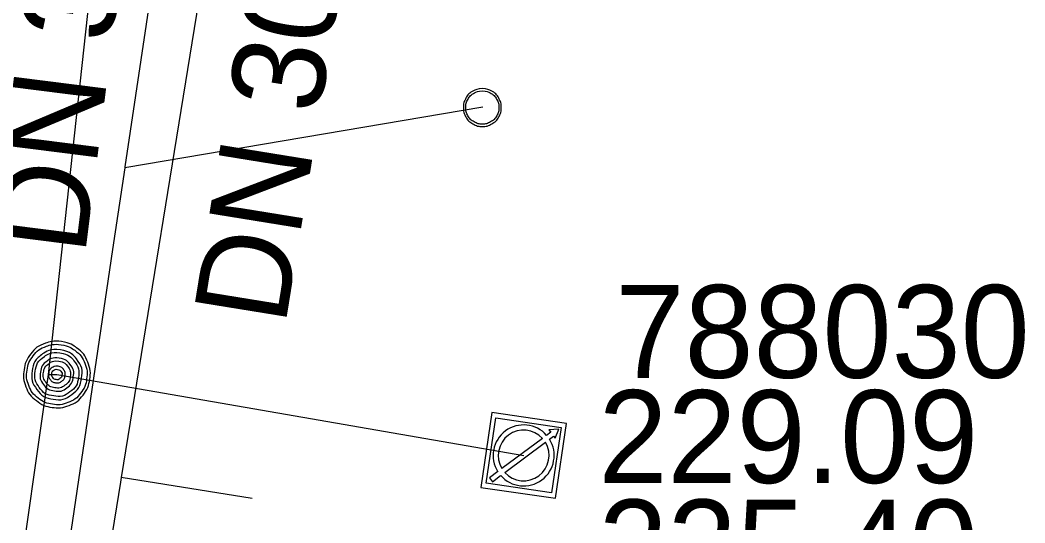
# Model space of a CAD drawing. Extents: x -595129 to -593591, y -1168385 to -1166898.
# Drawn here: x -594630.48 to -594615.33, y -1167150.4 to -1167142.81 of the extents above; entities that cross this region are included whole.
import ezdxf

# ---------------------------------------------------------------- set-up
doc = ezdxf.new("R2010")
doc.units = 0
for name, color, linetype in [('DA Kanalizační stoka popis', 7, 'Continuous'), ('Default', 7, 'Continuous'), ('Identifikace', 7, 'Continuous'), ('Kanalizační přípojka', 7, 'Continuous'), ('Kanalizační stoka', 7, 'Continuous'), ('Popis šachty', 7, 'Continuous'), ('V Odběrné místo', 7, 'Continuous'), ('V Přípojka', 7, 'Continuous'), ('V Řad', 7, 'Continuous')]:
    doc.layers.add(name, color=color, linetype=linetype)

msp = doc.modelspace()

# ---------------------------------------------------------------- linework, layer by layer
at = {"layer": 'Default'}
for points in [[(-594623.515, -1167143.849), (-594623.444, -1167143.849), (-594623.375, -1167143.885), (-594623.307, -1167143.922), (-594623.269, -1167143.991), (-594623.23, -1167144.059), (-594623.23, -1167144.134), (-594623.23, -1167144.208), (-594623.268, -1167144.276), (-594623.305, -1167144.343), (-594623.373, -1167144.381), (-594623.441, -1167144.419), (-594623.515, -1167144.419), (-594623.589, -1167144.419), (-594623.657, -1167144.381), (-594623.725, -1167144.343), (-594623.763, -1167144.276), (-594623.8, -1167144.208), (-594623.8, -1167144.134), (-594623.8, -1167144.059), (-594623.762, -1167143.991), (-594623.724, -1167143.922), (-594623.656, -1167143.885), (-594623.587, -1167143.849), (-594623.515, -1167143.849)], [(-594623.515, -1167143.884), (-594623.578, -1167143.884), (-594623.638, -1167143.916), (-594623.698, -1167143.948), (-594623.731, -1167144.008), (-594623.765, -1167144.068), (-594623.765, -1167144.134), (-594623.765, -1167144.199), (-594623.732, -1167144.258), (-594623.699, -1167144.317), (-594623.639, -1167144.35), (-594623.58, -1167144.383), (-594623.515, -1167144.383), (-594623.45, -1167144.383), (-594623.391, -1167144.35), (-594623.331, -1167144.317), (-594623.299, -1167144.258), (-594623.266, -1167144.199), (-594623.266, -1167144.134), (-594623.266, -1167144.068), (-594623.3, -1167144.008), (-594623.333, -1167143.948), (-594623.393, -1167143.916), (-594623.453, -1167143.884), (-594623.515, -1167143.884)], [(-594629.858, -1167147.664), (-594629.733, -1167147.682), (-594629.624, -1167147.764), (-594629.515, -1167147.845), (-594629.465, -1167147.974), (-594629.416, -1167148.103), (-594629.435, -1167148.232), (-594629.454, -1167148.361), (-594629.536, -1167148.469), (-594629.619, -1167148.577), (-594629.746, -1167148.626), (-594629.874, -1167148.674), (-594630.003, -1167148.655), (-594630.131, -1167148.636), (-594630.239, -1167148.553), (-594630.348, -1167148.471), (-594630.396, -1167148.344), (-594630.444, -1167148.216), (-594630.425, -1167148.088), (-594630.406, -1167147.958), (-594630.322, -1167147.848), (-594630.238, -1167147.739), (-594630.111, -1167147.692), (-594629.983, -1167147.646), (-594629.858, -1167147.664)], [(-594629.865, -1167147.711), (-594629.978, -1167147.694), (-594630.094, -1167147.736), (-594630.21, -1167147.778), (-594630.286, -1167147.878), (-594630.362, -1167147.977), (-594630.379, -1167148.094), (-594630.396, -1167148.211), (-594630.352, -1167148.326), (-594630.309, -1167148.441), (-594630.211, -1167148.516), (-594630.112, -1167148.591), (-594629.996, -1167148.608), (-594629.879, -1167148.625), (-594629.763, -1167148.582), (-594629.647, -1167148.538), (-594629.573, -1167148.44), (-594629.498, -1167148.342), (-594629.481, -1167148.226), (-594629.464, -1167148.108), (-594629.509, -1167147.991), (-594629.554, -1167147.874), (-594629.653, -1167147.801), (-594629.752, -1167147.727), (-594629.865, -1167147.711)], [(-594629.877, -1167147.788), (-594629.72, -1167147.811), (-594629.628, -1167147.935), (-594629.536, -1167148.06), (-594629.559, -1167148.214), (-594629.581, -1167148.368), (-594629.706, -1167148.461), (-594629.83, -1167148.553), (-594629.985, -1167148.531), (-594630.138, -1167148.508), (-594630.231, -1167148.384), (-594630.324, -1167148.259), (-594630.301, -1167148.106), (-594630.279, -1167147.951), (-594630.155, -1167147.858), (-594630.031, -1167147.765), (-594629.877, -1167147.788)], [(-594629.883, -1167147.833), (-594630.019, -1167147.814), (-594630.127, -1167147.895), (-594630.236, -1167147.976), (-594630.256, -1167148.111), (-594630.275, -1167148.246), (-594630.195, -1167148.355), (-594630.114, -1167148.464), (-594629.978, -1167148.483), (-594629.843, -1167148.503), (-594629.734, -1167148.422), (-594629.625, -1167148.341), (-594629.606, -1167148.206), (-594629.586, -1167148.071), (-594629.667, -1167147.962), (-594629.747, -1167147.853), (-594629.883, -1167147.833)], [(-594629.894, -1167147.912), (-594629.79, -1167147.927), (-594629.729, -1167148.01), (-594629.667, -1167148.093), (-594629.682, -1167148.196), (-594629.697, -1167148.299), (-594629.78, -1167148.36), (-594629.864, -1167148.422), (-594629.967, -1167148.407), (-594630.069, -1167148.392), (-594630.131, -1167148.309), (-594630.193, -1167148.226), (-594630.178, -1167148.124), (-594630.163, -1167148.021), (-594630.08, -1167147.959), (-594629.998, -1167147.897), (-594629.894, -1167147.912)], [(-594629.901, -1167147.958), (-594629.985, -1167147.946), (-594630.052, -1167147.996), (-594630.119, -1167148.046), (-594630.132, -1167148.13), (-594630.144, -1167148.213), (-594630.094, -1167148.281), (-594630.043, -1167148.348), (-594629.96, -1167148.36), (-594629.877, -1167148.372), (-594629.809, -1167148.322), (-594629.741, -1167148.272), (-594629.729, -1167148.188), (-594629.717, -1167148.105), (-594629.767, -1167148.037), (-594629.817, -1167147.97), (-594629.901, -1167147.958)], [(-594629.912, -1167148.036), (-594629.86, -1167148.043), (-594629.829, -1167148.085), (-594629.799, -1167148.126), (-594629.806, -1167148.178), (-594629.814, -1167148.229), (-594629.855, -1167148.26), (-594629.897, -1167148.291), (-594629.949, -1167148.283), (-594629.999, -1167148.276), (-594630.03, -1167148.234), (-594630.061, -1167148.193), (-594630.054, -1167148.141), (-594630.046, -1167148.09), (-594630.005, -1167148.059), (-594629.964, -1167148.028), (-594629.912, -1167148.036)], [(-594629.919, -1167148.082), (-594629.951, -1167148.077), (-594629.977, -1167148.096), (-594630.003, -1167148.115), (-594630.008, -1167148.148), (-594630.012, -1167148.18), (-594629.993, -1167148.206), (-594629.974, -1167148.232), (-594629.942, -1167148.237), (-594629.909, -1167148.242), (-594629.883, -1167148.222), (-594629.858, -1167148.203), (-594629.853, -1167148.171), (-594629.848, -1167148.138), (-594629.867, -1167148.112), (-594629.886, -1167148.087), (-594629.919, -1167148.082)]]:
    msp.add_open_spline(points, degree=3, dxfattribs=at)
at = {"layer": 'Kanalizační přípojka'}
for points in [[(-594623.506, -1167144.13), (-594628.906, -1167145.043)], [(-594626.988, -1167150.032), (-594628.962, -1167149.712)]]:
    msp.add_lwpolyline(points, dxfattribs=at)
at = {"layer": 'Kanalizační stoka'}
for points in [[(-594622.469, -1167109.695), (-594623.816, -1167117.996), (-594623.863, -1167118.283), (-594624.053, -1167119.457), (-594624.101, -1167119.753), (-594624.29, -1167120.918), (-594624.328, -1167121.155), (-594625.261, -1167126.9), (-594625.299, -1167127.137), (-594625.978, -1167131.322), (-594626.013, -1167131.539), (-594626.244, -1167132.961), (-594626.246, -1167132.971), (-594626.81, -1167136.445), (-594626.874, -1167136.84), (-594627.277, -1167139.327), (-594627.291, -1167139.416), (-594627.748, -1167142.23), (-594627.762, -1167142.318), (-594628.962, -1167149.712), (-594628.973, -1167149.781), (-594629.44, -1167152.663), (-594629.442, -1167152.673), (-594630.062, -1167156.493)], [(-594626.825, -1167131.013), (-594627.663, -1167136.707), (-594627.68, -1167136.824), (-594628.019, -1167139.129), (-594628.05, -1167139.333), (-594628.066, -1167139.435), (-594628.195, -1167140.282), (-594628.904, -1167145.028), (-594628.906, -1167145.043), (-594629.09, -1167146.275), (-594630.006, -1167152.472), (-594630.024, -1167152.591), (-594630.045, -1167152.719), (-594630.164, -1167153.457)]]:
    msp.add_lwpolyline(points, dxfattribs=at)
at = {"layer": 'V Odběrné místo'}
for p, q in [((-594622.607, -1167149.123), (-594623.22, -1167149.579)), ((-594623.177, -1167149.636), (-594622.564, -1167149.181))]:
    msp.add_line(p, q, dxfattribs=at)
for points in [[(-594623.538, -1167149.862), (-594622.41, -1167150.026), (-594622.246, -1167148.898), (-594623.374, -1167148.734)], [(-594623.458, -1167149.801), (-594623.313, -1167148.814), (-594622.326, -1167148.959), (-594622.471, -1167149.946)]]:
    msp.add_lwpolyline(points, close=True, dxfattribs=at)
for points in [[(-594622.503, -1167149.134), (-594622.441, -1167149.088), (-594622.417, -1167149.121), (-594622.362, -1167148.982), (-594622.511, -1167148.994), (-594622.484, -1167149.031), (-594622.546, -1167149.078)], [(-594623.281, -1167149.625), (-594623.406, -1167149.718), (-594623.364, -1167149.776), (-594623.239, -1167149.682)]]:
    msp.add_lwpolyline(points, dxfattribs=at)
for radius, start, end in [(0.46, 41.1545, 212.2087), (0.383, 42.0453, 211.318), (0.46, 221.1038, 32.259), (0.383, 221.9945, 31.315)]:
    msp.add_arc((-594622.892, -1167149.38), radius, start, end, dxfattribs=at)
at = {"layer": 'V Přípojka'}
msp.add_lwpolyline([(-594630.06, -1167148.16), (-594629.93, -1167148.16), (-594622.892, -1167149.38)], dxfattribs=at)
at = {"layer": 'V Řad'}
msp.add_lwpolyline([(-594620.641, -1167079.706), (-594621.282, -1167084.294), (-594621.49, -1167086.39), (-594622.13, -1167090.96), (-594623.141, -1167097.603), (-594623.691, -1167101.542), (-594624.15, -1167105.6), (-594624.21, -1167106.05), (-594625.836, -1167116.894), (-594625.854, -1167117.021), (-594626.112, -1167118.865), (-594627.094, -1167125.893), (-594627.519, -1167128.934), (-594627.85, -1167131.301), (-594628.024, -1167132.551), (-594628.278, -1167134.289), (-594629.266, -1167141.052), (-594629.36, -1167141.695), (-594630.06, -1167148.16), (-594630.57, -1167151.72), (-594631.97, -1167161.48), (-594632.196, -1167162.18)], dxfattribs=at)

# ---------------------------------------------------------------- texts
at = {"layer": 'DA Kanalizační stoka popis'}
for s, rotation, p in [('DN 300 BEO', 82.7924, (-594629.508, -1167146.378)), ('DN 300 KAM', 80.787, (-594626.489, -1167147.441))]:
    msp.add_text(s, height=1.4, rotation=rotation, dxfattribs=at).set_placement(p)
at = {"layer": 'Identifikace'}
msp.add_text('788030', height=1.4, dxfattribs=at).set_placement((-594621.509, -1167148.21))
at = {"layer": 'Popis šachty'}
for s, p in [('229.09', (-594621.764, -1167149.796)), ('225.40', (-594621.764, -1167151.446))]:
    msp.add_text(s, height=1.4, dxfattribs=at).set_placement(p)

doc.saveas('drawing.dxf')
